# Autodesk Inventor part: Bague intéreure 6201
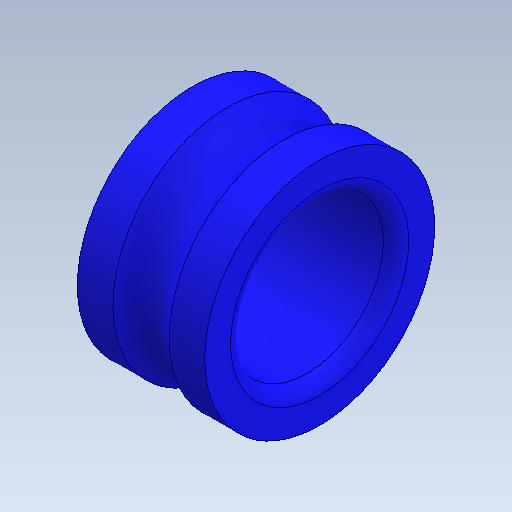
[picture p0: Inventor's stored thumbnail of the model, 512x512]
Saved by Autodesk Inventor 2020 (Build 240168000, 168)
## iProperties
Created: 2003-06
Part Number: Bague intéreure 6201
Material: Générique
Document SubType Name: Modeling
Designer: Bruno
Density: 1 g/cm^3
Appearance: Par défaut
Author: Bruno
Sending System: SolidWorks 2011
Last Author: frederic
Last Saved: 2012-02-20
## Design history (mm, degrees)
feature "Base-Révolution"
node "Solide1"
